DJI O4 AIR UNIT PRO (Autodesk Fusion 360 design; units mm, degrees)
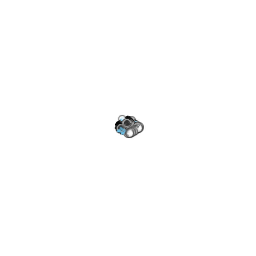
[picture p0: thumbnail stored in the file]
description: Part Number
part number: 91294A006_Black-Oxide Alloy Steel Hex Drive Flat Head Screw
base_feature "Base Feature1"
sketch "Sketch1" plane through (0, 0, 13) normal (0, 0, 1) x axis (-1, 0, 0)
  line L1 (14.9096, 13.75) -> (14.9096, -13.75)
  line L2 (-13.75, 14.9096) -> (13.75, 14.9096)
  line L3 (-14.9096, -13.75) -> (-14.9096, 13.75)
  line L4 (13.75, -14.9096) -> (-13.75, -14.9096)
  line L5 (10.4229, -7.2409) -> (7.2409, -10.4229)
  line L6 (15.407, -12.225) -> (10.4229, -7.2409)
  line L7 (7.2409, -10.4229) -> (13.5288, -16.7107)
  line L8 (18.2591, -15.0771) -> (7.2409, -10.4229)
  line L9 (15.0771, -18.2591) -> (10.4229, -7.2409)
  line L10 (0.325, -6.9877) -> (-0.325, -6.9877)
  line L11 (0.325, -26.4338) -> (0.325, -6.9877)
  line L12 (-0.325, -26.4338) -> (0.325, -26.4338)
  line L13 (-0.325, -6.9877) -> (-0.325, -26.4338)
  line L14 (0.325, -26.4338) -> (-0.325, -6.9877)
  line L15 (-0.325, -26.4338) -> (0.325, -6.9877)
  line L16 (-13.75, -16.7107) -> (13.75, -16.7107)
  line L17 (7.5, 7.5) -> (-7.5, 7.5)
  line L18 (7.5, -7.5) -> (7.5, 7.5)
  line L19 (-7.5, -7.5) -> (7.5, -7.5)
  line L20 (-7.5, 7.5) -> (-7.5, -7.5)
  line L21 (7.5, -7.5) -> (-7.5, 7.5)
  line L22 (-7.5, -7.5) -> (7.5, 7.5)
  line L23 (11.575, -6.9877) -> (11.575, -26.4338)
  line L24 (9.845, -26.4338) -> (9.845, -6.9877)
  line L25 (9.195, -6.9877) -> (9.195, -26.4338)
  line L26 (7.465, -26.4338) -> (7.465, -6.9877)
  line L27 (6.815, -6.9877) -> (6.815, -26.4338)
  line L28 (5.085, -26.4338) -> (5.085, -6.9877)
  line L29 (4.435, -6.9877) -> (4.435, -26.4338)
  line L30 (2.705, -26.4338) -> (2.705, -6.9877)
  line L31 (2.055, -6.9877) -> (2.055, -26.4338)
  line L32 (-2.055, -26.4338) -> (-2.055, -6.9877)
  line L33 (-2.705, -6.9877) -> (-2.705, -26.4338)
  line L34 (-4.435, -26.4338) -> (-4.435, -6.9877)
  line L35 (-5.085, -6.9877) -> (-5.085, -26.4338)
  line L36 (-6.815, -26.4338) -> (-6.815, -6.9877)
  line L37 (-7.465, -6.9877) -> (-7.465, -26.4338)
  line L38 (-9.195, -26.4338) -> (-9.195, -6.9877)
  line L39 (-9.845, -6.9877) -> (-9.845, -26.4338)
  line L40 (-11.575, -26.4338) -> (-11.575, -6.9877)
  line L41 (-12.225, -6.9877) -> (-12.225, -26.4338)
  line L42 (26.4338, 12.225) -> (6.9877, 12.225)
  line L43 (6.9877, 11.575) -> (26.4338, 11.575)
  line L44 (26.4338, 9.845) -> (6.9877, 9.845)
  line L45 (6.9877, 9.195) -> (26.4338, 9.195)
  line L46 (26.4338, 7.465) -> (6.9877, 7.465)
  line L47 (26.4338, 5.085) -> (6.9877, 5.085)
  line L48 (6.9877, -5.085) -> (26.4338, -5.085)
  line L49 (6.9877, -7.465) -> (26.4338, -7.465)
  line L50 (26.4338, -9.195) -> (6.9877, -9.195)
  line L51 (6.9877, -9.845) -> (26.4338, -9.845)
  line L52 (26.4338, -11.575) -> (6.9877, -11.575)
  line L53 (6.9877, -12.225) -> (26.4338, -12.225)
  line L54 (-12.225, 26.4338) -> (-12.225, 6.9877)
  line L55 (-11.575, 6.9877) -> (-11.575, 26.4338)
  line L56 (-9.845, 26.4338) -> (-9.845, 6.9877)
  line L57 (-9.195, 6.9877) -> (-9.195, 26.4338)
  line L58 (-7.465, 26.4338) -> (-7.465, 6.9877)
  line L59 (-6.815, 6.9877) -> (-6.815, 26.4338)
  line L60 (-5.085, 26.4338) -> (-5.085, 6.9877)
  line L61 (-4.435, 6.9877) -> (-4.435, 26.4338)
  line L62 (-2.705, 26.4338) -> (-2.705, 6.9877)
  line L63 (-2.055, 6.9877) -> (-2.055, 26.4338)
  line L64 (-0.325, 26.4338) -> (-0.325, 6.9877)
  line L65 (0.325, 6.9877) -> (0.325, 26.4338)
  line L66 (2.055, 26.4338) -> (2.055, 6.9877)
  line L67 (2.705, 6.9877) -> (2.705, 26.4338)
  line L68 (4.435, 26.4338) -> (4.435, 6.9877)
  line L69 (5.085, 6.9877) -> (5.085, 26.4338)
  line L70 (6.815, 26.4338) -> (6.815, 6.9877)
  line L71 (7.465, 6.9877) -> (7.465, 26.4338)
  line L72 (9.195, 26.4338) -> (9.195, 6.9877)
  line L73 (9.845, 6.9877) -> (9.845, 26.4338)
  line L74 (11.575, 26.4338) -> (11.575, 6.9877)
  line L75 (12.225, 6.9877) -> (12.225, 26.4338)
  line L76 (-15.407, -12.225) -> (-6.9877, -12.225)
  line L77 (-6.9877, -11.575) -> (-14.9096, -11.575)
  line L78 (-14.9096, -9.845) -> (-6.9877, -9.845)
  line L79 (-6.9877, -9.195) -> (-14.9096, -9.195)
  line L80 (-14.9096, -7.465) -> (-6.9877, -7.465)
  line L81 (-6.9877, -6.815) -> (-26.4338, -6.815)
  line L82 (-26.4338, -5.085) -> (-6.9877, -5.085)
  line L83 (-6.9877, -4.435) -> (-26.4338, -4.435)
  line L84 (-26.4338, -2.705) -> (-6.9877, -2.705)
  line L85 (-6.9877, -2.055) -> (-26.4338, -2.055)
  line L86 (-26.4338, -0.325) -> (-6.9877, -0.325)
  line L87 (-6.9877, 0.325) -> (-26.4338, 0.325)
  line L88 (-14.9096, 2.055) -> (-6.9877, 2.055)
  line L89 (-6.9877, 2.705) -> (-14.9096, 2.705)
  line L90 (-26.4338, 4.435) -> (-6.9877, 4.435)
  line L91 (-6.9877, 5.085) -> (-26.4338, 5.085)
  line L92 (-26.4338, 6.815) -> (-6.9877, 6.815)
  line L93 (-6.9877, 7.465) -> (-26.4338, 7.465)
  line L94 (-26.4338, 9.195) -> (-6.9877, 9.195)
  line L95 (-6.9877, 9.845) -> (-26.4338, 9.845)
  line L96 (-26.4338, 11.575) -> (-6.9877, 11.575)
  line L97 (-6.9877, 12.225) -> (-15.407, 12.225)
  line L98 (-3.3576, 0) -> (0, 0)
  line L99 (-3.3576, -4.6721) -> (-3.3576, 0)
  line L100 (0, -4.6721) -> (-3.3576, -4.6721)
  line L101 (0, 0) -> (0, -4.6721)
  line L102 (-7.2409, -10.4229) -> (-13.5288, -16.7107)
  line L103 (-15.407, -12.225) -> (-10.4229, -7.2409)
  line L104 (-7.2409, 10.4229) -> (-12.225, 15.407)
  line L105 (-15.407, 12.225) -> (-10.4229, 7.2409)
  line L106 (18.2591, 15.0771) -> (10.4229, 7.2409)
  line L107 (7.2409, 10.4229) -> (15.0771, 18.2591)
  line L108 (12.225, -10.5621) -> (12.225, -6.9877)
  line L109 (12.225, -26.4338) -> (12.225, -11.5071)
  line L110 (-13.75, 16.7107) -> (13.75, 16.7107)
  line L111 (-13.75, 16.4488) -> (-13.75, 16.7107)
  line L112 (13.75, 16.4488) -> (-13.75, 16.4488)
  line L113 (13.75, 16.7107) -> (13.75, 16.4488)
  line L114 (16.7107, 13.75) -> (16.7107, -13.75)
  line L115 (16.4488, 13.75) -> (16.7107, 13.75)
  line L116 (16.4488, -13.75) -> (16.4488, 13.75)
  line L117 (16.7107, -13.75) -> (16.4488, -13.75)
  line L118 (13.75, -16.7107) -> (-13.75, -16.7107)
  line L119 (13.75, -16.4488) -> (13.75, -16.7107)
  line L120 (-13.75, -16.4488) -> (13.75, -16.4488)
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  point P28 (12.75, -12.75)
  point P22 (12.75, -12.75)
  point P33 (0, -16.7107)
  point P40 (0, 0)
  point P1 (0, 0)
  point P185 (0, 0)
  point P24 (7.2409, -10.4229)
  point P191 (-7.2409, -10.4229)
  point P25 (10.4229, -7.2409)
  point P192 (-10.4229, -7.2409)
  point P201 (7.2409, 10.4229)
  point P198 (10.4229, 7.2409)
  point P26 (18.2591, -15.0771)
  point P199 (18.2591, 15.0771)
  point P27 (15.0771, -18.2591)
  point P200 (15.0771, 18.2591)
  point P195 (-7.2409, 10.4229)
  point P196 (-10.4229, 7.2409)
  point P203 (15.407, -12.225)
  point P204 (13.5288, -16.7107)
  point P205 (-13.5288, -16.7107)
  point P208 (-12.225, 15.407)
  point P209 (-14.9096, -7.465)
  point P210 (-14.9096, 2.055)
  point P211 (-14.9096, 2.705)
  point P212 (-14.9096, -11.575)
  point P213 (-14.9096, -9.195)
  point P214 (-14.9096, -9.845)
  point P215 (11.575, -10.8312)
  point P216 (10.8312, -11.575)
  point P218 (12.225, -11.5071)
  point P219 (11.6068, -11.575)
  point P220 (12.013, -11.0052)
  point P31 (0.325, -26.4338)
  point P32 (-0.325, -26.4338)
  point P38 (7.5, -7.5)
  point P39 (-7.5, -7.5)
  point P37 (7.5, 7.5)
  perpendicular L5 L6
  parallel L6 L7
  coincident L8 P28
  coincident L9 P28
  coincident P22 P28
  horizontal L10
  perpendicular L10 L11
  parallel L10 L12
  parallel L11 L13
  coincident L14 P33
  coincident L15 P33
  midpoint P33 L16
  horizontal L17
  perpendicular L17 L18
  parallel L17 L19
  parallel L18 L20
  coincident L21 P40
  coincident L22 P40
  coincident P1 P40
  horizontal L98
  vertical L99
  horizontal L100
  vertical L101
  coincident P1 P185
  symmetric P24 L101 P191
  symmetric P25 L101 P192
  symmetric P24 L98 P201
  symmetric P25 L98 P198
  symmetric P26 L98 P199
  symmetric P27 L98 P200
  symmetric L98 P191 P195
  symmetric L98 P192 P196
  coincident L53 P203
  coincident L16 P204
  coincident L16 P205
  coincident L54 P208
  coincident L3 P209
  coincident L3 P210
  coincident L3 P211
  coincident L3 P212
  coincident L3 P213
  coincident L3 P214
  coincident L23 P215
  coincident L52 P216
  coincident L9 P218
  collinear L108 L109
  coincident L52 P219
  coincident L9 P220
  dimension "d1" diameter = 4.5
  dimension "d2" diameter = 4.5
  dimension "d3" distance P26 P27 = 4.5
  dimension "d4" distance P31 P32 = 0.65
  dimension "d5" distance P38 P39 = 15
  dimension "d6" distance P37 P38 = 15
sketch "Sketch2" plane through (0, 0, 13) normal (0, 0, 1) x axis (-1, 0, 0)
  line L1 (7.465, 7.5) -> (6.815, 7.5)
  line L2 (7.465, 9.195) -> (7.465, 7.5)
  line L3 (7.8989, 9.195) -> (7.465, 9.195)
  line L4 (9.195, 7.465) -> (9.195, 7.8989)
  line L5 (10.647, 7.465) -> (9.195, 7.465)
  line L6 (12.377, 9.195) -> (10.647, 7.465)
  line L7 (14.9096, 9.195) -> (12.377, 9.195)
  line L8 (14.9096, 9.845) -> (14.9096, 9.195)
  line L9 (13.027, 9.845) -> (14.9096, 9.845)
  line L10 (14.757, 11.575) -> (13.027, 9.845)
  line L11 (14.9096, 11.575) -> (14.757, 11.575)
  line L12 (14.9096, 13.3814) -> (14.9096, 11.575)
  line L13 (11.575, 14.9096) -> (13.3814, 14.9096)
  line L14 (11.575, 14.757) -> (11.575, 14.9096)
  line L15 (9.845, 13.027) -> (11.575, 14.757)
  line L16 (9.845, 14.9096) -> (9.845, 13.027)
  line L17 (9.195, 14.9096) -> (9.845, 14.9096)
  line L18 (9.195, 12.377) -> (9.195, 14.9096)
  line L19 (7.465, 10.647) -> (9.195, 12.377)
  line L20 (7.465, 14.9096) -> (7.465, 10.647)
  line L21 (6.815, 14.9096) -> (7.465, 14.9096)
  line L22 (6.815, 7.5) -> (6.815, 14.9096)
  line L23 (6, 0) -> (0, 0)
  line L24 (10.647, -7.465) -> (9.195, -7.465)
  line L25 (9.195, -7.465) -> (10.647, -7.465)
  line L26 (9.195, -7.8989) -> (9.195, -7.465)
  line L27 (10.647, -7.8989) -> (9.195, -7.8989)
  line L28 (10.647, -7.465) -> (10.647, -7.8989)
  line L29 (12.377, -9.195) -> (10.647, -7.465)
  arc A1 centre (10, 10) radius 2.25 clockwise from (9.195, 7.8989) to (7.8989, 9.195)
  arc A2 centre (12.75, 12.75) radius 2.25 clockwise from (13.3814, 14.9096) to (14.9096, 13.3814)
  circle C1 centre (10, 10) radius 1
  circle C2 centre (12.75, 12.75) radius 1
  circle C3 centre (10, 10) radius 2.25
  circle C4 centre (-10, -10) radius 2.25
  circle C5 centre (-10, 10) radius 2.25
  circle C6 centre (10, -10) radius 2.25
  arc A3 centre (10, -10) radius 2.25 clockwise from (7.8989, -9.195) to (9.195, -7.8989)
  point P5 (7.8989, 9.195)
  point P30 (-7.8989, -9.195)
  point P1 (0, 0)
  point P37 (0, 0)
  point P8 (9.195, 7.465)
  point P39 (9.195, -7.465)
  point P9 (10.647, 7.465)
  point P40 (10.647, -7.465)
  point P34 (9.195, -7.8989)
  point P42 (9.195, -7.8989)
  point P44 (10.647, -7.465)
  point P10 (12.377, 9.195)
  point P45 (12.377, -9.195)
  concentric A1 C3
  coincident P5 C3
  coincident C4 P30
  concentric C6 A3
  coincident P1 P37
  horizontal L23
  symmetric P8 L23 P39
  symmetric P9 L23 P40
  horizontal L25
  vertical L26
  horizontal L27
  vertical L28
  coincident P34 P42
  symmetric P9 L23 P44
  symmetric P10 L23 P45
sketch "Sketch3"
  line L1 (-13.75, 16.75) -> (13.75, 16.75)
  line L2 (-16.75, -13.75) -> (-16.75, 13.75)
  line L3 (13.75, -16.75) -> (-13.75, -16.75)
  line L4 (16.75, 13.75) -> (16.75, -13.75)
  line L5 (-16.75, -16.75) -> (16.75, 16.75)
  line L6 (16.75, -16.75) -> (-16.75, 16.75)
  line L7 (-10, -10) -> (10, -10)
  line L8 (-10, 10) -> (-10, -10)
  line L9 (10, 10) -> (-10, 10)
  line L10 (10, -10) -> (10, 10)
  line L11 (-10, 10) -> (10, -10)
  line L12 (10, 10) -> (-10, -10)
  line L13 (-12.75, -12.75) -> (12.75, -12.75)
  line L14 (-12.75, 12.75) -> (-12.75, -12.75)
  line L15 (12.75, 12.75) -> (-12.75, 12.75)
  line L16 (12.75, -12.75) -> (12.75, 12.75)
  line L17 (-12.75, 12.75) -> (12.75, -12.75)
  line L18 (12.75, 12.75) -> (-12.75, -12.75)
  line L19 (6, 0) -> (0, 0)
  line L20 (6, 7) -> (6, 0)
  line L21 (0, 7) -> (6, 7)
  line L22 (0, 0) -> (0, 7)
  arc A1 centre (-13.75, -13.75) radius 3 clockwise from (-13.75, -16.75) to (-16.75, -13.75)
  arc A2 centre (13.75, -13.75) radius 3 clockwise from (16.75, -13.75) to (13.75, -16.75)
  arc A3 centre (13.75, 13.75) radius 3 clockwise from (13.75, 16.75) to (16.75, 13.75)
  arc A4 centre (-13.75, 13.75) radius 3 clockwise from (-16.75, 13.75) to (-13.75, 16.75)
  circle C1 centre (12.75, 12.75) radius 1
  circle C2 centre (10, 10) radius 1
  circle C3 centre (-10, 10) radius 1
  circle C4 centre (-12.75, 12.75) radius 1
  circle C5 centre (-12.75, -12.75) radius 1
  circle C6 centre (-10, -10) radius 1
  circle C7 centre (10, -10) radius 1
  circle C8 centre (12.75, -12.75) radius 1
  point P6 (0, 0)
  point P1 (0, 0)
  point P4 (-16.75, -16.75)
  point P5 (16.75, -16.75)
  point P2 (16.75, 16.75)
  point P3 (-16.75, 16.75)
  point P23 (0, 0)
  point P28 (0, 0)
  point P27 (12.75, 12.75)
  point P29 (12.75, 12.75)
  point P22 (10, 10)
  point P30 (10, 10)
  point P31 (0, 0)
  point P21 (-10, 10)
  point P20 (-10, -10)
  point P26 (-12.75, 12.75)
  point P25 (-12.75, -12.75)
  horizontal L1
  perpendicular L1 L2
  parallel L1 L3
  parallel L2 L4
  coincident L5 P6
  coincident L6 P6
  coincident P1 P6
  coincident P4 L2
  coincident P4 L3
  tangent L2 A1
  tangent L3 A1
  coincident P5 L3
  coincident P5 L4
  tangent L3 A2
  tangent L4 A2
  equal A1 A2
  coincident P2 L4
  coincident P2 L1
  tangent L4 A3
  tangent L1 A3
  equal A1 A3
  coincident P3 L1
  coincident P3 L2
  tangent L1 A4
  tangent L2 A4
  equal A1 A4
  horizontal L7
  perpendicular L7 L8
  parallel L7 L9
  parallel L8 L10
  coincident L11 P23
  coincident L12 P23
  coincident P6 P23
  horizontal L13
  perpendicular L13 L14
  parallel L13 L15
  parallel L14 L16
  coincident L17 P28
  coincident L18 P28
  coincident P23 P28
  coincident P27 P29
  coincident P22 P30
  horizontal L19
  vertical L20
  horizontal L21
  vertical L22
  coincident P6 P31
  symmetric C1 L22 C4
  symmetric C2 L22 C3
  symmetric C1 L19 C8
  symmetric C2 L19 C7
  symmetric L19 C3 C6
  symmetric L19 C4 C5
  dimension "d7" distance P4 P5 = 33.5
  dimension "d8" distance P3 P4 = 33.5
  dimension "d9" radius A1 = 3
  dimension "d15" distance P21 P22 = 20
  dimension "d16" distance P20 P21 = 20
  dimension "d17" distance P26 P27 = 25.5
  dimension "d18" distance P25 P26 = 25.5
  dimension "d19" diameter C1 = 2
  dimension "d20" diameter C2 = 2
sketch "Sketch4" plane through (0, 0, 11.8) normal (0, 0, 1) x axis (-1, 0, 0)
  line L1 (16.1414, -7.465) -> (10.647, -7.465)
  line L2 (16.1414, -5.5218) -> (16.1414, -7.465)
  line L3 (7.815, -5.5218) -> (16.1414, -5.5218)
  line L4 (7.0632, 4.77) -> (7.0632, -4.77)
  line L5 (16.1414, 5.5218) -> (7.815, 5.5218)
  line L6 (16.1414, 7.465) -> (16.1414, 5.5218)
  line L7 (10.647, 7.465) -> (16.1414, 7.465)
  line L8 (11.591, 8.409) -> (10.647, 7.465)
  line L9 (9.195, 7.465) -> (9.195, 7.8989)
  line L10 (7.5, 7.465) -> (9.195, 7.465)
  line L11 (7.5, 7.5) -> (7.5, 7.465)
  line L12 (7.465, 7.5) -> (7.5, 7.5)
  line L13 (6.815, 7.5) -> (7.465, 7.5)
  line L14 (5.085, 7.5) -> (6.815, 7.5)
  line L15 (4.435, 7.5) -> (5.085, 7.5)
  line L16 (2.705, 7.5) -> (4.435, 7.5)
  line L17 (2.055, 7.5) -> (2.705, 7.5)
  line L18 (0.325, 7.5) -> (2.055, 7.5)
  line L19 (-0.325, 7.5) -> (0.325, 7.5)
  line L20 (-2.055, 7.5) -> (-0.325, 7.5)
  line L21 (-2.705, 7.5) -> (-2.055, 7.5)
  line L22 (-4.435, 7.5) -> (-2.705, 7.5)
  line L23 (-5.085, 7.5) -> (-4.435, 7.5)
  line L24 (-6.815, 7.5) -> (-5.085, 7.5)
  line L25 (-7.465, 7.5) -> (-6.815, 7.5)
  line L26 (-7.5, 7.5) -> (-7.465, 7.5)
  line L27 (-7.5, 7.465) -> (-7.5, 7.5)
  line L28 (-7.5, 6.815) -> (-7.5, 7.465)
  line L29 (-7.5, 5.085) -> (-7.5, 6.815)
  line L30 (-7.5, 4.435) -> (-7.5, 5.085)
  line L31 (-7.5, 2.705) -> (-7.5, 4.435)
  line L32 (-7.5, 2.055) -> (-7.5, 2.705)
  line L33 (-7.5, 0.325) -> (-7.5, 2.055)
  line L34 (-7.5, -0.325) -> (-7.5, 0.325)
  line L35 (-7.5, -2.055) -> (-7.5, -0.325)
  line L36 (-7.5, -2.705) -> (-7.5, -2.055)
  line L37 (-7.5, -4.435) -> (-7.5, -2.705)
  line L38 (-7.5, -5.085) -> (-7.5, -4.435)
  line L39 (-7.5, -6.815) -> (-7.5, -5.085)
  line L40 (-7.5, -7.465) -> (-7.5, -6.815)
  line L41 (-7.5, -7.5) -> (-7.5, -7.465)
  line L42 (-7.465, -7.5) -> (-7.5, -7.5)
  line L43 (-6.815, -7.5) -> (-7.465, -7.5)
  line L44 (-5.085, -7.5) -> (-6.815, -7.5)
  line L45 (-4.435, -7.5) -> (-5.085, -7.5)
  line L46 (-2.705, -7.5) -> (-4.435, -7.5)
  line L47 (-2.055, -7.5) -> (-2.705, -7.5)
  line L48 (-0.325, -7.5) -> (-2.055, -7.5)
  line L49 (0.325, -7.5) -> (-0.325, -7.5)
  line L50 (2.055, -7.5) -> (0.325, -7.5)
  line L51 (2.705, -7.5) -> (2.055, -7.5)
  line L52 (4.435, -7.5) -> (2.705, -7.5)
  line L53 (5.085, -7.5) -> (4.435, -7.5)
  line L54 (6.815, -7.5) -> (5.085, -7.5)
  line L55 (7.465, -7.5) -> (6.815, -7.5)
  line L56 (7.5, -7.5) -> (7.465, -7.5)
  line L57 (7.5, -7.465) -> (7.5, -7.5)
  line L58 (9.195, -7.465) -> (7.5, -7.465)
  line L59 (9.195, -7.8989) -> (9.195, -7.465)
  line L60 (10.647, -7.465) -> (11.591, -8.409)
  line L61 (10.5, -10.75) -> (-10.5, -10.75)
  line L62 (10.5, 10.75) -> (10.5, -10.75)
  line L63 (-10.5, 10.75) -> (10.5, 10.75)
  line L64 (-10.5, -10.75) -> (-10.5, 10.75)
  line L65 (10.5, 10.75) -> (-10.5, -10.75)
  line L66 (-10.5, 10.75) -> (10.5, -10.75)
  line L67 (-5.085, -7.5) -> (-5.085, -16.4541)
  line L68 (-6.815, -7.5) -> (-5.085, -7.5)
  line L69 (-6.815, -16.4541) -> (-6.815, -7.5)
  line L70 (-5.085, -16.4541) -> (-6.815, -16.4541)
  line L71 (-2.705, -7.5) -> (-2.705, -16.4541)
  line L72 (-4.435, -7.5) -> (-2.705, -7.5)
  line L73 (-4.435, -16.4541) -> (-4.435, -7.5)
  line L74 (-2.705, -16.4541) -> (-4.435, -16.4541)
  line L75 (-0.325, -7.5) -> (-0.325, -16.4541)
  line L76 (-2.055, -7.5) -> (-0.325, -7.5)
  line L77 (-2.055, -16.4541) -> (-2.055, -7.5)
  line L78 (-0.325, -16.4541) -> (-2.055, -16.4541)
  line L79 (2.055, -7.5) -> (2.055, -16.4541)
  line L80 (0.325, -7.5) -> (2.055, -7.5)
  line L81 (0.325, -16.4541) -> (0.325, -7.5)
  line L82 (2.055, -16.4541) -> (0.325, -16.4541)
  line L83 (4.435, -7.5) -> (4.435, -16.4541)
  line L84 (2.705, -7.5) -> (4.435, -7.5)
  line L85 (2.705, -16.4541) -> (2.705, -7.5)
  line L86 (4.435, -16.4541) -> (2.705, -16.4541)
  line L87 (6.815, -7.5) -> (6.815, -16.4541)
  line L88 (5.085, -7.5) -> (6.815, -7.5)
  line L89 (5.085, -16.4541) -> (5.085, -7.5)
  line L90 (6.815, -16.4541) -> (5.085, -16.4541)
  line L91 (5.085, 16.4541) -> (6.815, 16.4541)
  line L92 (5.085, 7.5) -> (5.085, 16.4541)
  line L93 (6.815, 7.5) -> (5.085, 7.5)
  line L94 (6.815, 16.4541) -> (6.815, 7.5)
  line L95 (2.705, 16.4541) -> (4.435, 16.4541)
  line L96 (2.705, 7.5) -> (2.705, 16.4541)
  line L97 (4.435, 7.5) -> (2.705, 7.5)
  line L98 (4.435, 16.4541) -> (4.435, 7.5)
  line L99 (0.325, 16.4541) -> (2.055, 16.4541)
  line L100 (0.325, 7.5) -> (0.325, 16.4541)
  line L101 (2.055, 7.5) -> (0.325, 7.5)
  line L102 (2.055, 16.4541) -> (2.055, 7.5)
  line L103 (-2.055, 14.9096) -> (-2.055, 8.6994)
  line L104 (-2.055, 16.4541) -> (-0.325, 16.4541)
  line L105 (-2.055, 7.5) -> (-2.055, 16.4541)
  line L106 (-0.325, 7.5) -> (-2.055, 7.5)
  line L107 (-0.325, 16.4541) -> (-0.325, 7.5)
  line L108 (-4.435, 16.4541) -> (-2.705, 16.4541)
  line L109 (-4.435, 7.5) -> (-4.435, 16.4541)
  line L110 (-2.705, 7.5) -> (-4.435, 7.5)
  line L111 (-2.705, 16.4541) -> (-2.705, 7.5)
  line L112 (-6.815, 16.4541) -> (-5.085, 16.4541)
  line L113 (-6.815, 7.5) -> (-6.815, 16.4541)
  line L114 (-5.085, 7.5) -> (-6.815, 7.5)
  line L115 (-5.085, 16.4541) -> (-5.085, 7.5)
  closed curve K1 centre (7.9146, -4.6704)
  closed curve K2 centre (7.9146, 4.6704)
  arc A1 centre (10, 10) radius 2.25 clockwise from (11.591, 8.409) to (9.195, 7.8989)
  arc A2 centre (10, -10) radius 2.25 clockwise from (9.195, -7.8989) to (11.591, -8.409)
  point P74 (0, 0)
  point P1 (0, 0)
  point P72 (10.5, 10.75)
  point P73 (-10.5, 10.75)
  point P71 (10.5, -10.75)
  horizontal L61
  perpendicular L61 L62
  parallel L61 L63
  parallel L62 L64
  coincident L65 P74
  coincident L66 P74
  coincident P1 P74
  dimension "d21" distance P72 P73 = 21
  dimension "d22" distance P71 P72 = 21.5
sketch "Sketch5" plane through (0, 0, 13) normal (0, 0, 1) x axis (-1, 0, 0)
  line L1 (-4.435, 14.9096) -> (-4.435, 7.5)
  line L2 (-5.085, 14.9096) -> (-4.435, 14.9096)
  line L3 (-5.085, 7.5) -> (-5.085, 14.9096)
  line L4 (-6.815, 7.5) -> (-5.085, 7.5)
  line L5 (-6.815, 14.9096) -> (-6.815, 7.5)
  line L6 (-7.465, 14.9096) -> (-6.815, 14.9096)
  line L7 (-7.465, 10.647) -> (-7.465, 14.9096)
  line L8 (-9.195, 12.377) -> (-7.465, 10.647)
  line L9 (-9.195, 14.9096) -> (-9.195, 12.377)
  line L10 (-9.845, 14.9096) -> (-9.195, 14.9096)
  line L11 (-9.845, 13.027) -> (-9.845, 14.9096)
  line L12 (-11.575, 14.757) -> (-9.845, 13.027)
  line L13 (-11.575, 14.9096) -> (-11.575, 14.757)
  line L14 (-13.3814, 14.9096) -> (-11.575, 14.9096)
  line L15 (-14.9096, 11.575) -> (-14.9096, 13.3814)
  line L16 (-14.757, 11.575) -> (-14.9096, 11.575)
  line L17 (-13.027, 9.845) -> (-14.757, 11.575)
  line L18 (-14.9096, 9.845) -> (-13.027, 9.845)
  line L19 (-14.9096, 9.195) -> (-14.9096, 9.845)
  line L20 (-12.377, 9.195) -> (-14.9096, 9.195)
  line L21 (-10.647, 7.465) -> (-12.377, 9.195)
  line L22 (-14.9096, 7.465) -> (-10.647, 7.465)
  line L23 (-14.9096, 6.815) -> (-14.9096, 7.465)
  line L24 (-7.5, 6.815) -> (-14.9096, 6.815)
  line L25 (-7.5, 5.085) -> (-7.5, 6.815)
  line L26 (-14.9096, 5.085) -> (-7.5, 5.085)
  line L27 (-14.9096, 4.435) -> (-14.9096, 5.085)
  line L28 (-7.5, 4.435) -> (-14.9096, 4.435)
  line L29 (-7.5, 2.705) -> (-7.5, 4.435)
  line L30 (-14.9096, 2.705) -> (-7.5, 2.705)
  line L31 (-14.9096, 2.055) -> (-14.9096, 2.705)
  line L32 (-7.5, 2.055) -> (-14.9096, 2.055)
  line L33 (-7.5, 0.325) -> (-7.5, 2.055)
  line L34 (-14.9096, 0.325) -> (-7.5, 0.325)
  line L35 (-14.9096, -0.325) -> (-14.9096, 0.325)
  line L36 (-7.5, -0.325) -> (-14.9096, -0.325)
  line L37 (-7.5, -2.055) -> (-7.5, -0.325)
  line L38 (-14.9096, -2.055) -> (-7.5, -2.055)
  line L39 (-14.9096, -2.705) -> (-14.9096, -2.055)
  line L40 (-7.5, -2.705) -> (-14.9096, -2.705)
  line L41 (-7.5, -4.435) -> (-7.5, -2.705)
  line L42 (-14.9096, -4.435) -> (-7.5, -4.435)
  line L43 (-14.9096, -5.085) -> (-14.9096, -4.435)
  line L44 (-7.5, -5.085) -> (-14.9096, -5.085)
  line L45 (-7.5, -6.815) -> (-7.5, -5.085)
  line L46 (-14.9096, -6.815) -> (-7.5, -6.815)
  line L47 (-14.9096, -7.465) -> (-14.9096, -6.815)
  line L48 (-10.647, -7.465) -> (-14.9096, -7.465)
  line L49 (-12.377, -9.195) -> (-10.647, -7.465)
  line L50 (-14.9096, -9.195) -> (-12.377, -9.195)
  line L51 (-14.9096, -9.845) -> (-14.9096, -9.195)
  line L52 (-13.027, -9.845) -> (-14.9096, -9.845)
  line L53 (-14.757, -11.575) -> (-13.027, -9.845)
  line L54 (-14.9096, -11.575) -> (-14.757, -11.575)
  line L55 (-11.575, -14.9096) -> (-13.3814, -14.9096)
  line L56 (-11.575, -14.757) -> (-11.575, -14.9096)
  line L57 (-9.845, -13.027) -> (-11.575, -14.757)
  line L58 (-9.845, -14.9096) -> (-9.845, -13.027)
  line L59 (-9.195, -14.9096) -> (-9.845, -14.9096)
  line L60 (-9.195, -12.377) -> (-9.195, -14.9096)
  line L61 (-7.465, -10.647) -> (-9.195, -12.377)
  line L62 (-7.465, -14.9096) -> (-7.465, -10.647)
  line L63 (-6.815, -14.9096) -> (-7.465, -14.9096)
  line L64 (-6.815, -7.5) -> (-6.815, -14.9096)
  line L65 (-5.085, -7.5) -> (-6.815, -7.5)
  line L66 (-5.085, -14.9096) -> (-5.085, -7.5)
  line L67 (-4.435, -14.9096) -> (-5.085, -14.9096)
  line L68 (-4.435, -7.5) -> (-4.435, -14.9096)
  line L69 (-2.705, -7.5) -> (-4.435, -7.5)
  line L70 (-2.705, -14.9096) -> (-2.705, -7.5)
  line L71 (-2.055, -14.9096) -> (-2.705, -14.9096)
  line L72 (-2.055, -7.5) -> (-2.055, -14.9096)
  line L73 (-0.325, -7.5) -> (-2.055, -7.5)
  line L74 (-0.325, -14.9096) -> (-0.325, -7.5)
  line L75 (0.325, -14.9096) -> (-0.325, -14.9096)
  line L76 (0.325, -7.5) -> (0.325, -14.9096)
  line L77 (2.055, -7.5) -> (0.325, -7.5)
  line L78 (2.055, -14.9096) -> (2.055, -7.5)
  line L79 (2.705, -14.9096) -> (2.055, -14.9096)
  line L80 (2.705, -7.5) -> (2.705, -14.9096)
  line L81 (4.435, -7.5) -> (2.705, -7.5)
  line L82 (4.435, -14.9096) -> (4.435, -7.5)
  line L83 (5.085, -14.9096) -> (4.435, -14.9096)
  line L84 (5.085, -7.5) -> (5.085, -14.9096)
  line L85 (6.815, -7.5) -> (5.085, -7.5)
  line L86 (6.815, -14.9096) -> (6.815, -7.5)
  line L87 (7.465, -14.9096) -> (6.815, -14.9096)
  line L88 (7.465, -10.647) -> (7.465, -14.9096)
  line L89 (9.195, -12.377) -> (7.465, -10.647)
  line L90 (9.195, -14.9096) -> (9.195, -12.377)
  line L91 (9.845, -14.9096) -> (9.195, -14.9096)
  line L92 (9.845, -13.027) -> (9.845, -14.9096)
  line L93 (11.575, -14.757) -> (9.845, -13.027)
  line L94 (11.575, -14.9096) -> (11.575, -14.757)
  line L95 (14.9096, -11.575) -> (14.9096, -13.3814)
  line L96 (14.757, -11.575) -> (14.9096, -11.575)
  line L97 (13.027, -9.845) -> (14.757, -11.575)
  line L98 (14.9096, -9.845) -> (13.027, -9.845)
  line L99 (14.9096, -9.195) -> (14.9096, -9.845)
  line L100 (12.377, -9.195) -> (14.9096, -9.195)
  line L101 (10.647, -7.465) -> (12.377, -9.195)
  line L102 (14.9096, -7.465) -> (10.647, -7.465)
  line L103 (14.9096, -5.085) -> (14.9096, -7.465)
  line L104 (7.5, -5.085) -> (14.9096, -5.085)
  line L105 (7.5, 5.085) -> (7.5, -5.085)
  line L106 (14.9096, 5.085) -> (7.5, 5.085)
  line L107 (14.9096, 7.465) -> (14.9096, 5.085)
  line L108 (10.647, 7.465) -> (14.9096, 7.465)
  line L109 (12.377, 9.195) -> (10.647, 7.465)
  line L110 (14.9096, 9.195) -> (12.377, 9.195)
  line L111 (14.9096, 9.845) -> (14.9096, 9.195)
  line L112 (13.027, 9.845) -> (14.9096, 9.845)
  line L113 (14.757, 11.575) -> (13.027, 9.845)
  line L114 (14.9096, 11.575) -> (14.757, 11.575)
  line L115 (14.9096, 13.3814) -> (14.9096, 11.575)
  line L116 (11.575, 14.9096) -> (13.3814, 14.9096)
  line L117 (11.575, 14.757) -> (11.575, 14.9096)
  line L118 (9.845, 13.027) -> (11.575, 14.757)
  line L119 (9.845, 14.9096) -> (9.845, 13.027)
  line L120 (9.195, 14.9096) -> (9.845, 14.9096)
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  point P168 (7.5, -7.465)
  point P179 (7.5, -7.465)
  point P196 (1.19, -7.5)
  coincident P168 P179
  midpoint L77 P196
extrude "Extrude1" new body sketch "Sketch3" profile of L1 L2 L3 L4 A1 A2 A3 A4 L7 L8 L9 L10 L13 L14 L15 L16 C1 C2 L19 L20 L21 L22 C3 C4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 blind 13
canvas "Canvas1"
draft "Draft1" "d12" -1.5 (= "Angle1") "d13" 0 (= "Angle2")
chamfer "Chamfer1" distance 1.5
canvas "Canvas2"
extrude "Extrude2" cut sketch "Sketch1" against normal blind 1.7
extrude "Extrude3" cut sketch "Sketch5" against normal blind 1.2
extrude "Extrude4" add of existing geometry blind 1.7
draft "Draft2" "d41" 20 (= "Angle1") "d42" 0 (= "Angle2")
fillet "Fillet1" radius 0.8
extrude "Extrude5" cut of existing geometry blind -0.015
extrude "Extrude6" add of existing geometry blind 1.5
delete_face "DeleteFace1"
delete_face "DeleteFace2"
extrude "Extrude7" cut sketch "Sketch2" profile of L4 L5 L6 C3 C6 L24 L25 L26 L28 L29 against normal blind 1.2
chamfer "Chamfer2" distance 1
extrude "Extrude8" cut of existing geometry blind -0.035
chamfer "Chamfer3" distance 1
offset_faces "OffsetFaces1" distance -0.141
extrude "Extrude9" add sketch "Sketch4" profile of L14 L16 L18 L20 L22 L24 L44 L46 L48 L50 L52 L54 L61 L63 L67 L68 L69 L71 L72 L73 L75 L76 L77 L79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 blind -0.4 from offset -0.25
position "Position1"
base_feature "Base Feature1"
base_feature "Base Feature1"
base_feature "Base Feature1"
base_feature "Base Feature1"
base_feature "Base Feature1"
base_feature "Base Feature1"
base_feature "Base Feature1"
base_feature "Base Feature1"
base_feature "Base Feature1"
base_feature "Base Feature1"
base_feature "Base Feature1"
base_feature "Base Feature1"
base_feature "Base Feature1"
base_feature "Base Feature1"
base_feature "Base Feature1"
position "Position2"
extrude "Extrude10" cut sketch "Reconstructed-Sketch1 (1)" blind -0.25
extrude "Extrude11" add sketch "Reconstructed-Sketch2 (1)" blind -1
delete_face "DeleteFace3"
delete_face "DeleteFace4"
delete_face "DeleteFace5"
fillet "Fillet2" radius 1
base_feature "Base Feature1"
extrude "Extrude12" cut sketch "Reconstructed-Sketch3 (1)" blind -3
delete_face "DeleteFace6"
offset_faces "OffsetFaces2" distance 0.1
offset_faces "OffsetFaces3" distance 0.1
fillet "Fillet3" radius 0.3
extrude "Extrude13" add sketch "Reconstructed-Sketch4 (1)" blind 0.1
extrude "Extrude14" add sketch "Reconstructed-Sketch5 (1)" blind 0.1
split "Split1"
remove_body "RemoveBody1"
offset_faces "OffsetFaces4" distance -0.2
mirror "Mirror1" mirrorStitchTolerance 0.1
mirror "Mirror2" mirrorStitchTolerance 0.1
extrude "Extrude15" cut sketch "Reconstructed-Sketch6" blind -2
rectangular_pattern "R-Pattern1" uSpaceDistance -1.75 vSpaceDistance 0
extrude "Extrude16" cut sketch "Reconstructed-Sketch7" blind -0.2
offset_faces "OffsetFaces5" distance 0.2
offset_faces "OffsetFaces6" distance -0.2
fillet "Fillet4" radius 0.5
extrude "Extrude17" cut of existing geometry blind -2
delete_face "DeleteFace7"
delete_face "DeleteFace8"
delete_face "DeleteFace9"
delete_face "DeleteFace10"
delete_face "DeleteFace11"
offset_faces "OffsetFaces7" distance 0.1
delete_face "DeleteFace12"
delete_face "DeleteFace13"
delete_face "DeleteFace14"
circular_pattern "C-Pattern1"
delete_face "DeleteFace15"
rectangular_pattern "R-Pattern2" uSpaceDistance -1.73 vSpaceDistance 0
delete_face "DeleteFace16"
delete_face "DeleteFace17"
delete_face "DeleteFace18"
canvas "Canvas3"
extrude "Extrude18" add sketch "Reconstructed-Sketch8" + "Reconstructed-Sketch9" blind 0.01
extrude "Extrude19" add sketch "Reconstructed-Sketch10" blind 0.01
move_face "MoveFace1"
move_face "MoveFace2"
move_face "MoveFace3"
extrude "Extrude20" add sketch "Reconstructed-Sketch11" blind -0.01
move_face "MoveFace4"
move_face "MoveFace5"
offset_faces "OffsetFaces8" distance -0.03
offset_faces "OffsetFaces9" distance 0.01
position "Position3"
base_feature "Base Feature1" bodies "USB C Outer", "USB C Inner", "Solder", "Solder (1)", "Solder (2)", "Solder (3)"
split "Split1" bodies "USB C Outer (1)", "USB C Outer (2)", "USB C Outer (3)", "USB C Outer (4)", "USB C Outer (5)", "USB C Outer (6)", "USB C Outer (7)", "USB C Outer (8)"
split "Split2" bodies "USB C Outer (13)", "USB C Outer (14)"
split "Split3" bodies "USB C Outer (15)", "USB C Outer (16)"
remove_body "RemoveBody1"
remove_body "RemoveBody2"
remove_body "RemoveBody3"
remove_body "RemoveBody4"
remove_body "RemoveBody5"
remove_body "RemoveBody6"
remove_body "RemoveBody7"
remove_body "RemoveBody8"
remove_body "RemoveBody9"
remove_body "RemoveBody10"
remove_body "RemoveBody11"
remove_body "RemoveBody12"
remove_body "RemoveBody13"
remove_body "RemoveBody14"
remove_body "RemoveBody15"
remove_body "RemoveBody16"
remove_body "RemoveBody17"
remove_body "RemoveBody18"
remove_body "RemoveBody19"
remove_body "RemoveBody20"
split "Split4" bodies "USB C Inner (1)", "USB C Inner (2)", "USB C Inner (3)", "USB C Inner (4)", "USB C Inner (5)", "USB C Inner (6)", "USB C Inner (7)", "USB C Inner (8)"
split "Split5" bodies "USB C Inner (13)", "USB C Inner (14)", "USB C Inner (15)", "USB C Inner (16)", "USB C Inner (17)", "USB C Inner (18)", "USB C Inner (19)", "USB C Inner (20)"
extrude "Extrude1" add of existing geometry blind 0.6 named "d1_1" bodies "USB C Inner (13)", "USB C Inner (14)", "USB C Inner (15)", "USB C Inner (16)", "USB C Inner (17)", "USB C Inner (18)", "USB C Inner (19)", "USB C Inner (20)"
delete_face "DeleteFace1"
delete_face "DeleteFace2"
extrude "Extrude21" cut blind -6.55
delete_face "DeleteFace19"
delete_face "DeleteFace20"
offset_faces "OffsetFaces10" distance -0.1
fillet "Fillet5" radius 0.15
position "Position4"
mirror "Mirror1" mirrorStitchTolerance 0.1
mirror "Mirror2" mirrorStitchTolerance 0.1
thread "Thread1" ThreadOffset 0 ThreadLength 10
offset_faces "OffsetFaces11" distance -0.08
delete_face "DeleteFace23"
fillet "Fillet7" radius 0.2
fillet "Fillet8" radius 0.5
fillet "Fillet6" radius 0.2
delete_face "DeleteFace21"
delete_face "DeleteFace22"
fillet "Fillet9" radius 0.15
draft "Draft3" "d160" 30 (= "Angle1") "d161" 0 (= "Angle2")
fillet "Fillet10" radius 0.2
fillet "Fillet11" radius 0.2
delete_face "DeleteFace27"
delete_face "DeleteFace28"
delete_face "DeleteFace29"
delete_face "DeleteFace30"
delete_face "DeleteFace31"
delete_face "DeleteFace32"
delete_face "DeleteFace33"
delete_face "DeleteFace34"
delete_face "DeleteFace35"
delete_face "DeleteFace36"
delete_face "DeleteFace37"
delete_face "DeleteFace38"
delete_face "DeleteFace39"
delete_face "DeleteFace40"
delete_face "DeleteFace41"
delete_face "DeleteFace42"
delete_face "DeleteFace43"
delete_face "DeleteFace44"
fillet "Fillet13" radius 0.2
fillet "Fillet14" radius 0.2
offset_faces "OffsetFaces13" distance -7.211
offset_faces "OffsetFaces14" distance 1
split "Split2"
remove_body "RemoveBody2"
offset_faces "OffsetFaces15" distance 4
split "Split3"
remove_body "RemoveBody3"
remove_body "RemoveBody4"
remove_body "RemoveBody5"
remove_body "RemoveBody6"
remove_body "RemoveBody7"
remove_body "RemoveBody8"
delete_face "DeleteFace45"
rectangular_pattern "R-Pattern3" uSpaceDistance 1.75 vSpaceDistance 0
extrude "Extrude22" add sketch "Reconstructed-Sketch12" blind -3
rectangular_pattern "R-Pattern4" uSpaceDistance 1.8 vSpaceDistance 0
delete_face "DeleteFace46"
move_face "MoveFace6"
move_face "MoveFace7"
offset_faces "OffsetFaces16" distance -1.5
fillet "Fillet15" radius 1
move_face "MoveFace8"
split "Split4"
chamfer "Chamfer4" distance 0.1
extrude "Extrude23" add sketch "Reconstructed-Sketch13" + "Reconstructed-Sketch14" blind 0.01
move_face "MoveFace9" TranslateX 0.1 TranslateY 0 TranslateZ 0.3
scale "Scale1"
draft "Draft4" "d202" 1.5 (= "Angle1") "d203" 0 (= "Angle2")
fillet "Fillet17" radius 0.2
fillet "Fillet16" radius 0.5
extrude "Extrude24" add sketch "Reconstructed-Sketch15" + "Reconstructed-Sketch16" blind 0.01
fillet "Fillet12" radius 0.2
move_face "MoveFace10" TranslateX 0 TranslateY 0 TranslateZ -0.3
extrude "Extrude25" add sketch "Reconstructed-Sketch17" blind 0.01
fillet "Fillet19" radius 0.2
fillet "Fillet20" radius 0.2
fillet "Fillet21" radius 0.2
fillet "Fillet22" radius 0.2
fillet "Fillet23" radius 0.2
fillet "Fillet24" radius 0.1
offset_faces "OffsetFaces17" distance 3
delete_face "DeleteFace47"
delete_face "DeleteFace48"
rectangular_pattern "R-Pattern5" uSpaceDistance -1.75 vSpaceDistance 0
fillet "Fillet25" radius 0.05
component_from_bodies "Body->Comp1"
component_from_bodies "Body->Comp2"
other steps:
base_feature "Base Feature1"
base_feature "Base Feature1"
create_component "CreateComponent1"
create_component "CreateComponent2"
create_component "CreateComponent3"
create_component "CreateComponent4"
create_component "CreateComponent5"
create_component "CreateComponent6"
create_component "CreateComponent7"
create_component "CreateComponent8"
create_component "CreateComponent9"
create_component "CreateComponent10"
create_component "CreateComponent11"
create_component "CreateComponent12"
create_component "CreateComponent13"
create_component "CreateComponent14"
create_component "CreateComponent15"
create_component "CreateComponent1"
remove_body "RemoveBody9"
create_component "CreateComponent2"
remove_body "RemoveBody10"
create_component "CreateComponent3"
create_component "CreateComponent4"
create_component "CreateComponent5"
named bodies: "USB C Outer", "USB C Inner", "Solder", "Solder (1)", "Solder (2)", "Solder (3)", "USB C Outer (1)", "USB C Outer (2)", "USB C Outer (3)", "USB C Outer (4)", "USB C Outer (5)", "USB C Outer (6)", "USB C Outer (7)", "USB C Outer (8)", "USB C Outer (9)", "USB C Outer (10)", "USB C Outer (11)", "USB C Outer (12)", "USB C Outer (13)", "USB C Outer (14)", "USB C Outer (15)", "USB C Outer (16)", "USB C Inner (1)", "USB C Inner (2)", "USB C Inner (3)", "USB C Inner (4)", "USB C Inner (5)", "USB C Inner (6)", "USB C Inner (7)", "USB C Inner (8)", "USB C Inner (9)", "USB C Inner (10)", "USB C Inner (11)", "USB C Inner (12)", "USB C Inner (13)", "USB C Inner (14)", "USB C Inner (15)", "USB C Inner (16)", "USB C Inner (17)", "USB C Inner (18)", "USB C Inner (19)", "USB C Inner (20)", "USB C Inner (21)", "USB C Inner (22)", "USB C Inner (23)", "USB C Inner (24)"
